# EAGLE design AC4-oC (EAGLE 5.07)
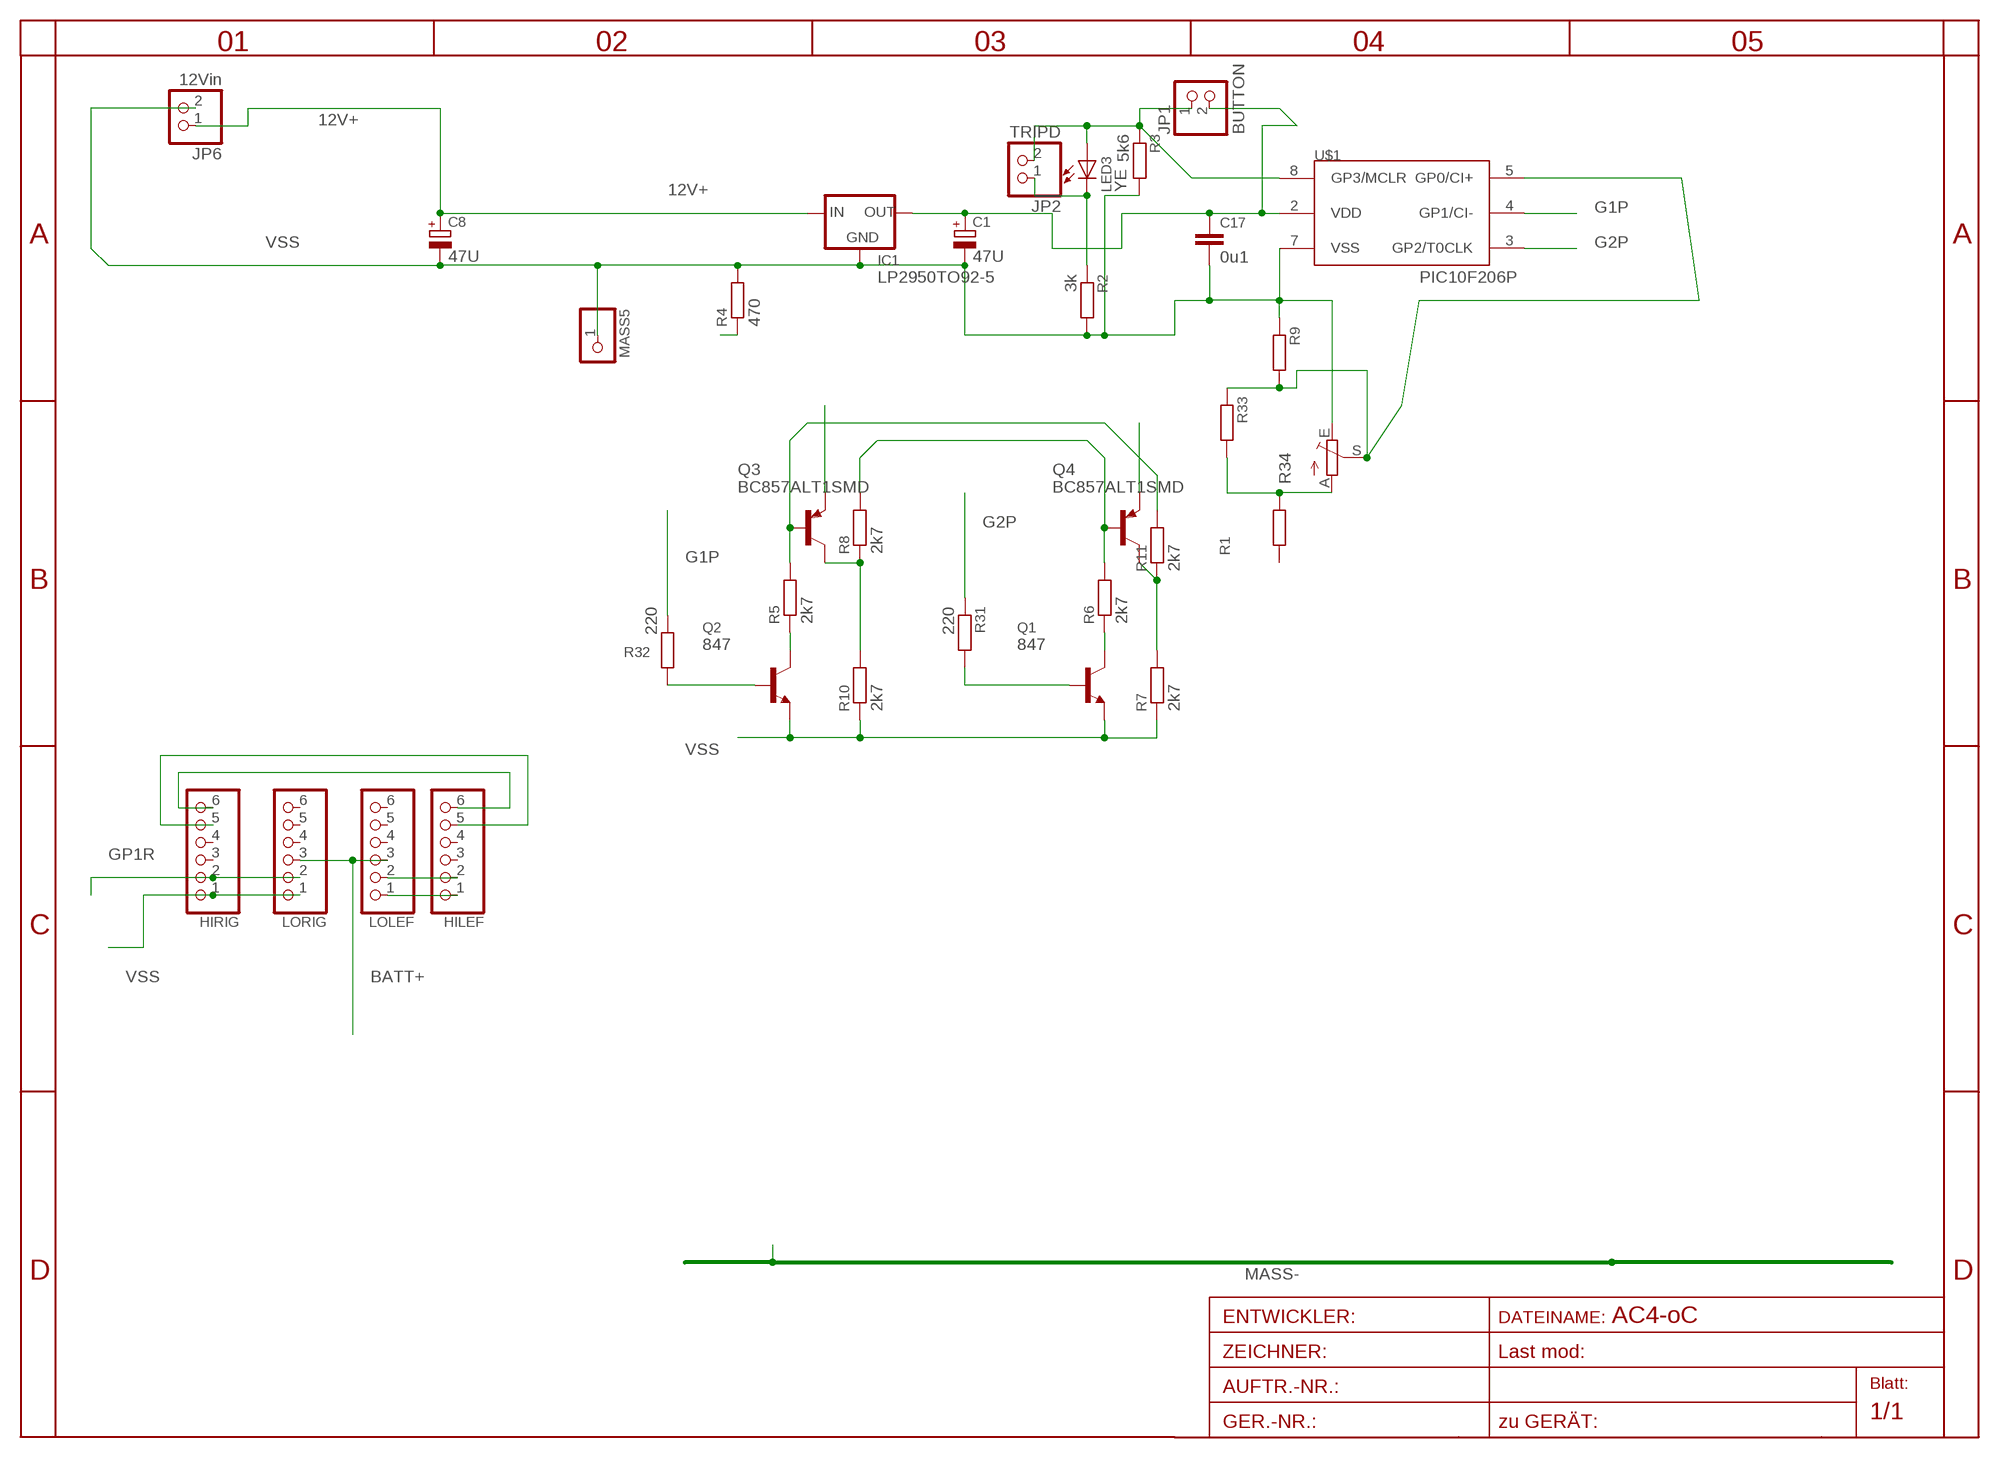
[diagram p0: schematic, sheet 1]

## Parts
C1  47U  CPOL-EUE5-6  [E5-6]
C8  47U  CPOL-EUE5-5  [E5-5]
C17  0u1  C-EUC1206  [C1206]
HILEF  PINHD-1X6  [1X06BOX]
HIRIG  PINHD-1X6  [1X06BOX]
IC1  LP2950TO92-5  [T092-5]
JP1  BUTTON  PINHD-1X2/90  [1X02/90]
JP2  TRIPD  PINHD-1X2/90  [1X02/90]
JP6  12Vin  PINHD-1X2STR  [1X02]
LED3  YE  LEDCHIPLED_1206  [CHIPLED_1206]
LOLEF  PINHD-1X6  [1X06BOX]
LORIG  PINHD-1X6  [1X06BOX]
MASS5  PINHD-1X11MM6  [1X1MM8]
Q1  847  BC847ALT1SMD  [SOT23]
Q2  847  BC847ALT1SMD  [SOT23]
Q3  BC857ALT1SMD  [SOT23-BEC]
Q4  BC857ALT1SMD  [SOT23-BEC]
R1  R-EU_0207/35  [0207/35]
R2  3k  R-EU_R0805  [R0805]
R3  5k6  R-EU_R0805  [R0805]
R4  470  R-EU_0204/5  [0204/5]
R5  2k7  R-EU_R0805  [R0805]
R6  2k7  R-EU_R0805  [R0805]
R7  2k7  R-EU_R0805  [R0805]
R8  2k7  R-EU_R0805  [R0805]
R9  R-EU_R0805  [R0805]
R10  2k7  R-EU_R0805  [R0805]
R11  2k7  R-EU_R0805  [R0805]
R31  220  R-EU_R1206  [R1206]
R32  220  R-EU_R1206  [R1206]
R33  R-EU_R0805  [R0805]
R34  TRIM_EU-S64W  [S64W]
U$1  PIC10F206P  [DIL8]

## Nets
12V+: C8.+ IC1.3(IN) JP6.1 Q3.E Q4.E
BATT+: LOLEF.3 LORIG.3
G1P: R32.1 U$1.4(GP1/CI-)
G2P: R31.1 U$1.3(GP2/T0CLK)
GP1R: HIRIG.2 LORIG.2 Q3.C R8.1 R10.2
GP2R: HILEF.2 LOLEF.2 Q4.C R7.2 R11.1
GP3: HILEF.6 HIRIG.6 JP1.1 JP2.2 LED3.A R3.1 U$1.8(GP3/MCLR)
N$1: R9.2 R33.1 R34.S U$1.5(GP0/CI+)
N$2: Q2.1(B) R32.2
N$4: Q2.3(C) R5.1
N$5: Q3.B R5.2 R11.2
N$6: Q1.1(B) R31.2
N$9: Q4.B R6.2 R8.2
N$11: Q1.3(C) R6.1
N$15: JP2.1 LED3.C R2.1
N$34: R4.1
N$42: R1.1 R33.2 R34.A
VDD: C1.+ C17.1 HILEF.5 HIRIG.5 IC1.1(OUT) JP1.2 U$1.2(VDD)
VSS: C1.- C8.- C17.2 HILEF.1 HIRIG.1 IC1.2(GND) JP6.2 LOLEF.1 LORIG.1 MASS5.1 Q1.2(E) Q2.2(E) R2.2 R3.2 R4.2 R7.1 R9.1 R10.1 R34.E U$1.7(VSS)
Unconnected: HILEF.3 HILEF.4 HIRIG.3 HIRIG.4 LOLEF.4 LOLEF.5 LOLEF.6 LORIG.4 LORIG.5 LORIG.6 R1.2

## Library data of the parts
C1 C8 = rcl-2:CPOL-EU: POLARIZED CAPACITOR, European symbol
C17 = rcl-2:C-EU: CAPACITOR, European symbol
HILEF HIRIG LOLEF LORIG = pinhead:PINHD-1X6: PIN HEADER
IC1 = v-reg:LP2950?*: Source: http://cache.national.com/ds/LP/LP2950.pdf
JP1 JP2 JP6 = pinhead:PINHD-1X2: PIN HEADER
LED3 = led:LED: LED
MASS5 = pinhead:PINHD-1X1: PIN HEADER
Q1 Q2 = transistor-npn:BC847*: NPN Transistor
Q3 Q4 = transistor-pnp:BC857*: PNP Transistror
R1-R11 R31-R33 = rcl-2:R-EU_: RESISTOR, European symbol
R34 = pot:TRIM_EU-: POTENTIOMETER
U$1 = microchip-5:PIC10F2*: uPC nW 0,25/0,5k Program Flash memory Comparator

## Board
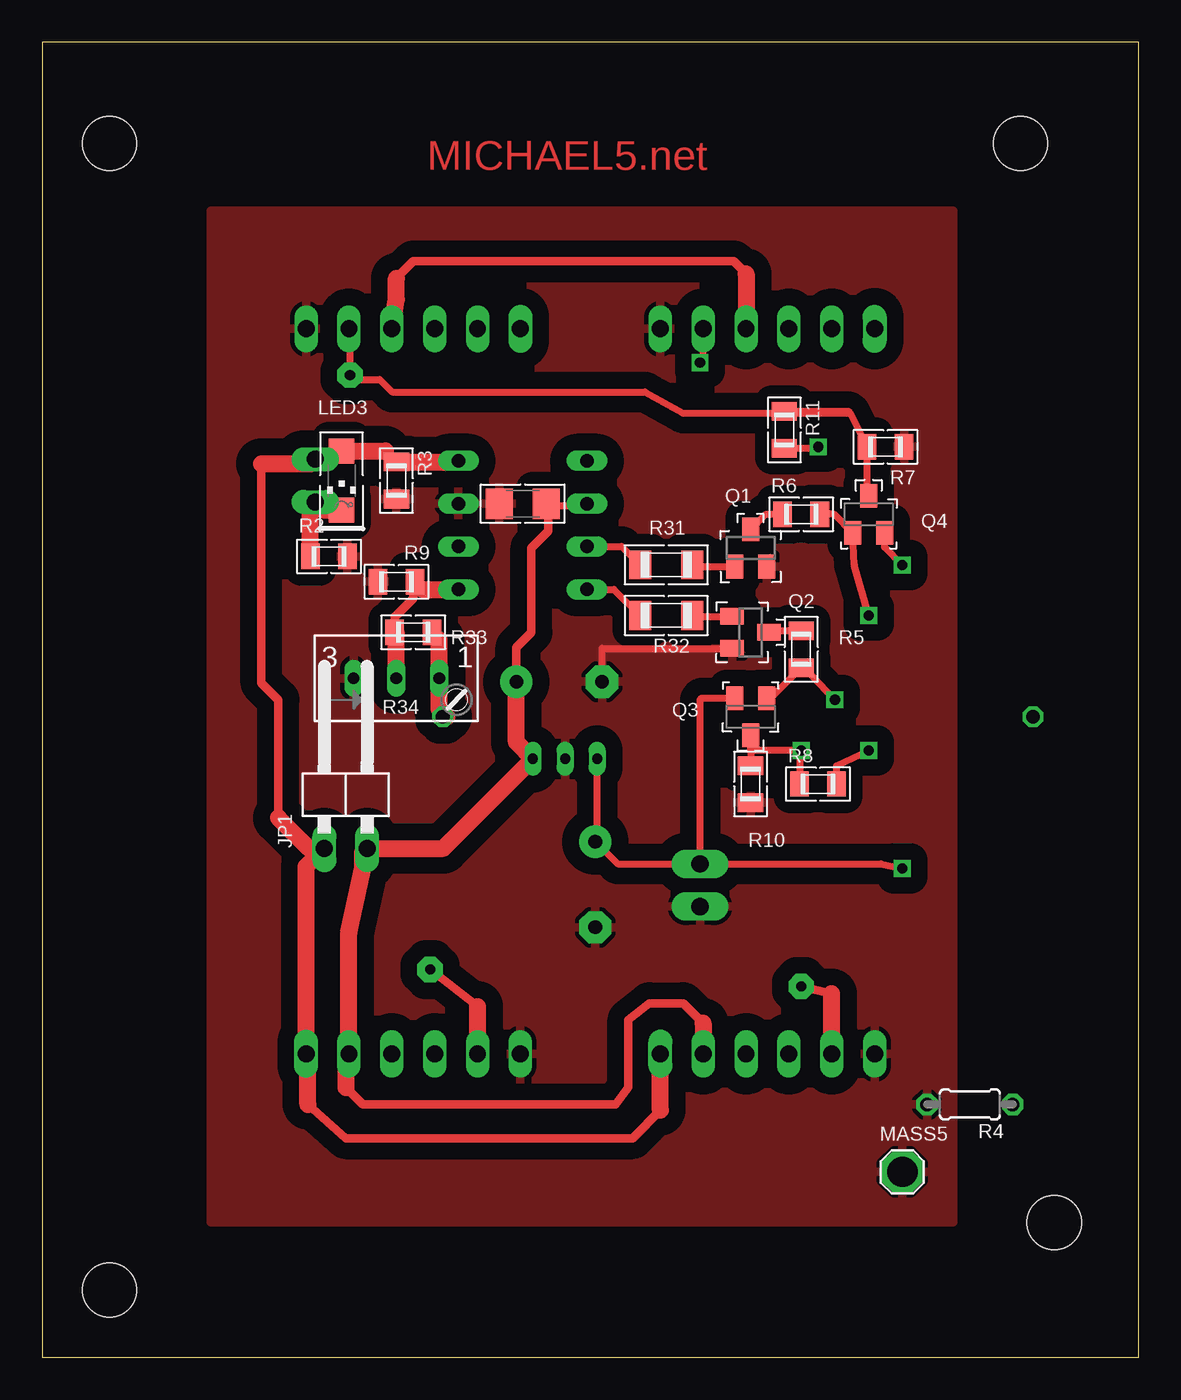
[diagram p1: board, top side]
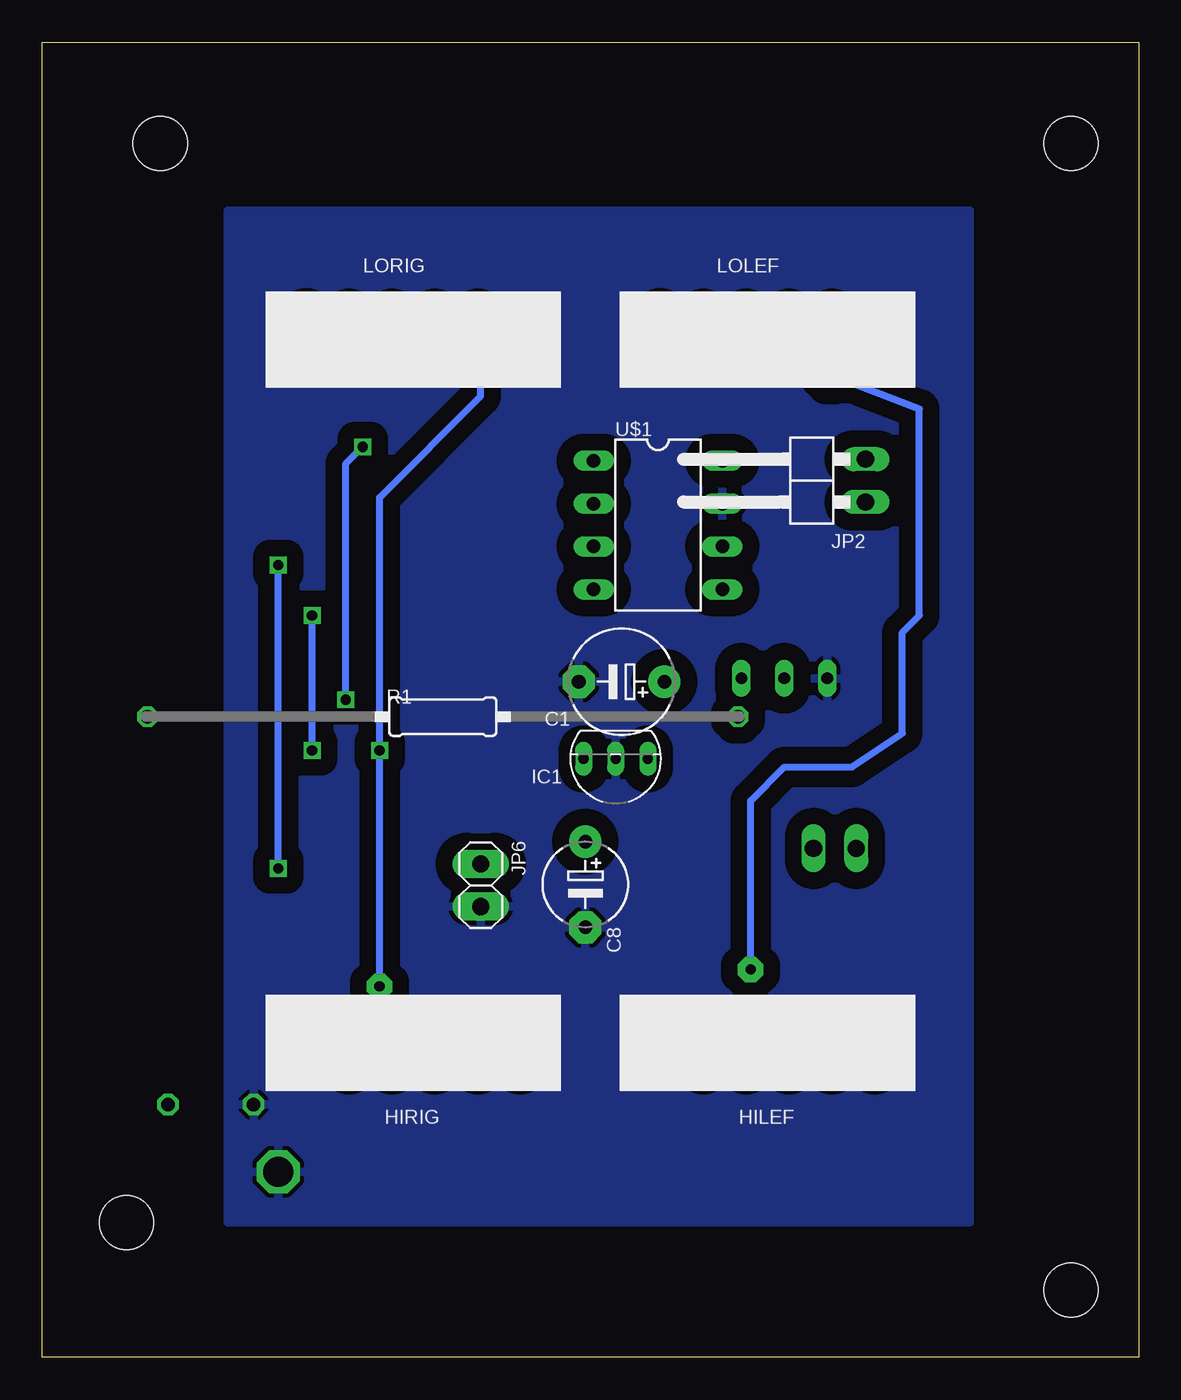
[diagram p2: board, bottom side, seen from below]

Size 65 x 78 mm. Coordinates in mm from the lower left corner, seen from the top.
Outline: 0,0 65,0 65,78 0,78 0,0
Copper layers (1*16): Top 0.035mm / dielectric 1.5mm / Bottom 0.035mm
Design rules "default *": minimum track width 12mil, minimum drill 24mil, track to track 8mil, track to pad 8mil, pad to pad 8mil, via to via 8mil, smd to smd 8mil, copper to edge 40mil, drill to drill 8mil, minimum pad ring 8mil, minimum via ring 8mil, stop-mask expansion 4mil, vias tented up to drill 0mil, thermal gap 10mil
Holes 3.2 mm at 4,72 4,4 58,72 60,8

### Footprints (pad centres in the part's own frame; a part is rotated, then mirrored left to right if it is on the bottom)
E5-6 = drill 0.813 pad 1.905 round: + -2.54,0 | drill 0.813 pad 1.905 octagon: - 2.54,0
E5-5 = drill 0.813 pad 1.905 round: + -2.54,0 | drill 0.813 pad 1.905 octagon: - 2.54,0
C1206 = smd 1.6 x 1.8: 1 -1.4,0; 2 1.4,0
1X06BOX = drill 1 long: 1 -6.35,0; 2 -3.81,0; 3 -1.27,0; 4 1.27,0; 5 3.81,0 | drill 1.016 long: 6 6.35,0
T092-5 = drill 0.6 pad 0.813 long: 1 -1.905,0; 2 0,0; 3 1.905,0
1X02/90 = drill 1.016 long: 1 -1.27,-3.81; 2 1.27,-3.81
1X02 = drill 1.016 pad 1.676 long: 1 -1.27,0; 2 1.27,0
CHIPLED_1206 = smd 1.5 x 1.5: A 0,-1.75; C 0,1.75
1X1MM8 = drill 1.8 pad 2.54 octagon: 1 0,0
SOT23 = smd 1 x 1.4: 1 -0.95,-1.1; 2 0.95,-1.1; 3 0,1.1
SOT23-BEC = smd 1 x 1.4: B -0.95,-1.1; C 0,1.1; E 0.95,-1.1
0207/35 = drill 0.813 octagon: 1 -17.5,0; 2 17.5,0
R0805 = smd 1.1 x 1.5: 1 -1.1,0; 2 1.1,0
0204/5 = drill 0.8 pad 1.27 octagon: 1 -2.54,0; 2 2.54,0
R1206 = smd 1.3 x 1.7: 1 -1.55,0; 2 1.55,0
S64W = drill 0.7 long: A 2.54,1.27; E -2.54,1.27; S 0,1.27
DIL8 = drill 0.8 long: 1 -3.81,-3.81; 2 -1.27,-3.81; 3 1.27,-3.81; 4 3.81,-3.81; 5 3.81,3.81; 6 1.27,3.81; 7 -1.27,3.81; 8 -3.81,3.81

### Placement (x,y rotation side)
C1  30.65,40.07 180 bottom
C8  32.8,28.05 270 bottom
C17  28.49,50.63 180 top
HILEF  22,18 0 bottom
HIRIG  43,18 0 bottom
IC1  31,35.5 180 bottom
JP1  18,34 0 top
JP2  20,52 90 bottom
JP6  39,28 270 bottom
LED3  17.75,52 180 top
LOLEF  22,61 180 bottom
LORIG  43,61 180 bottom
MASS5  51,11 0 top
Q1  42,48 0 top
Q2  42,43 270 top
Q3  42,38 180 top
Q4  49,50 0 top
R1  41.25,38 180 bottom
R2  17,47.5 0 top
R3  21,52 270 top
R4  55,15 180 top
R5  45,42 270 top
R6  45,50 0 top
R7  50,54 180 top
R8  46,34 0 top
R9  21,46 0 top
R10  42,34 90 top
R11  44,55 270 top
R31  37,47 0 top
R32  37,44 0 top
R33  22,43 0 top
R34  21,39 0 top
U$1  28.49,49.36 270 bottom

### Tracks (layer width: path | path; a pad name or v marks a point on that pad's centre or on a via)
12V+  (via drill 0.6)
  Top 0.406: 32.91,30.7 IC1.3 | Q4.E 49.95,48.05 v51,47 | Q3.E 39.1,39.1 39,39 JP6.1 | JP6.1 49.73,29.27 v51,29 | JP6.1 34.11,29.27 C8.+
  Top 0.5: C8.+ 32.91,30.7
  Bottom 0.406: v51,29 v51,47
BATT+
  Top 0.5: 41.73,64.27 41,65 22,65 21,64
  Top 1: 41.73,64.27 LORIG.3 | 21,64 21,62.73 LOLEF.3
G1P
  Top 0.406: U$1.4 33.9,45.55 R32.1
G2P
  Top 0.406: U$1.3 34.36,48.09 R31.1
GP1R  (via drill 0.6, 0.6 pad 1.5)
  Top 0.406: 42,36 v45,36 44.9,35.9 R8.1 | LORIG.2 39.19,59.19 v39,59 | 42,36 R10.2 | 42,36 Q3.C
  Top 0.5: 46.81,21.56 v45,22
  Top 1: HIRIG.2 46.81,21.56
  Bottom 0.406: v45,22 v45,36 45,51 39,57 v39,59
GP2R  (via drill 0.6 pad 1.5)
  Top 0.406: 47.9,56 38,56 35.75,57.25 20.75,57.25 20,58 18.5,58 v18.25,58.25 18.25,60.94 LOLEF.2 | 47.9,56 R7.2 48.9,51.2 Q4.C | R11.1 47.8,56.1 47.9,56
  Top 0.5: 25.81,20.81 v23,23
  Top 1: HILEF.2 25.81,20.81
  Bottom 0.406: v23,23 23,33 21,35 17,35 14,37 14,43 13,44 13,56.25 v18.25,58.25
GP3
  Top 0.5: 36.65,14.65 35,13 18,13 15.75,15 | 15.75,17.65 HILEF.6 | JP1.1 15.81,30.19 | 14,32 14,39 13,40 13,53 | 15.92,53 JP2.2 17.27,53.27 LED3.A | 20.35,53.75 R3.1 | 24.61,53.1 U$1.8
  Top 1: 36.65,14.65 HIRIG.6 | 15.75,15 15.75,17.65 | HILEF.6 15.65,29.11 JP1.1 | 15.81,30.19 14,32 | 13,53 15.92,53 | LED3.A 20.35,53.75 | R3.1 24.61,53.1
N$1
  Top 0.5: 21,42.9 R33.1 20.9,43.9 22,45 22,45.9 R9.2 22.55,45.55
  Top 1: R34.S 21,42.9 | 22.55,45.55 U$1.5
N$2
  Top 0.406: Q2.1 38.6,43.95 R32.2
N$4
  Top 0.406: R5.1 43.2,43.1 Q2.3
N$5  (via drill 0.6)
  Top 0.406: Q3.B 43.2,39.1 R5.2 45.1,41 v47,39 | R11.2 45.9,53.9 v46,54
  Bottom 0.406: v46,54 47,53 v47,39
N$6
  Top 0.406: Q1.1 38.65,46.9 R31.2
N$9  (via drill 0.6)
  Top 0.406: R6.2 46.95,50 Q4.B 48.15,47 v49,44 | R8.2 47.1,35.1 v49,36
  Bottom 0.406: v49,36 v49,44
N$11
  Top 0.406: R6.1 42.9,50 Q1.3
N$15
  Top 0.5: 15.9,50.44 JP2.1 16.67,50.25
  Top 1: R2.1 15.9,50.44 | 16.67,50.25 LED3.C
N$42
  Top 0.5: 23.54,42.56 R33.2 | 24,38 23.54,38.46
  Top 1: 23.54,42.56 R34.A 23.54,38.46 | R1.1 24,38
VDD
  Top 0.406: 30,50.52 32.19,50.52 U$1.2
  Top 0.5: 19,29.92 JP1.2 | C1.+ 28.11,42.11 29,43 29,48 30,49 30,50.52 C17.1 | 39.19,19.81 38,21 36,21 34.75,20 34.75,16 34,15 19,15 18,16 | 18,17.81 HILEF.5
  Top 1: HILEF.5 18.19,25.19 19,29 19,29.92 | JP1.2 23.79,30.19 IC1.1 28.11,36.48 C1.+ | 39.19,19.81 HIRIG.5 | 18,17.81 18,16
VSS
  Top 0.406: Q2.2 33.19,42.05 C1.-
  pour Top (isolate 1): 10,68 54,68 54,8 10,8
  pour Bottom (isolate 1): 10,68 54,68 54,8 10,8

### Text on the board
Top: MICHAEL5.net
